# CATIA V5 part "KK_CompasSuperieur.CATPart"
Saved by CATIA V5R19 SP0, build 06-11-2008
Part number: Compas superieur
Bounding box of the stored display mesh (mm): x -108 to 108, y 1328 to 1660.464, z -2320.464 to -2052
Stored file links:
  G:\Khaled_CFAO_2011\ST2M\ST2M_GR2\aboulegue\Khaled\CAD_thinkMOTION\KK_CompasSuperieur.CATPart
  G:\Khaled_CFAO_2011\ST2M\ST2M_GR2\aboulegue\Khaled\CAD_thinkMOTION\KK_Train_Atterrissage.CATProduct
  G:\Khaled_CFAO_2011\ST2M\ST2M_GR2\aboulegue\CFAO_aboulegue\CFAO_aboulegue_fichiers_catia\Squelette_amortisseur.CATPart
  G:\Khaled_CFAO_2011\ST2M\ST2M_GR2\aboulegue\Khaled\CAD_thinkMOTION\KK_SqueletteCompas_Superieur.CATPart
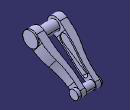
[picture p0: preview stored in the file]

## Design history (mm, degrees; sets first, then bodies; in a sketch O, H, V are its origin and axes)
Set1
  Line1 to Line3: linked copy from another document
  Plane1 "Plan compas superieur": linked copy from another document
  Point1: linked copy from another document
  Point2: linked copy from another document
  Plane2 "Plan compas superieur 2": linked copy from another document
Body1 (main body)
  Sketch1 on Plane2, origin (0, -512.64, -683.52), H (-1, 0, 0), V (0, -0.8, 0.6)
    line L1 (-50, -2312.8) -> (-50, -2408.8)
    arc A1 centre (714.0325, -2408.8) radius 764.0325 from (-50, -2408.8) to (-40.1962, -2530.8031) ccw
    point P4 (-40.1962, -2530.8031)
    arc A2 centre (-670.7452, -2632.8) radius 638.7452 from (-40.1962, -2530.8031) to (-32, -2632.8) cw
    line L2 (-32, -2632.8) -> (-32, -2728.8)
    line L3 (-32, -2728.8) -> (-64, -2728.8)
    line L4 (-64, -2728.8) -> (-64, -2632.8)
    arc A3 centre (-482.0557, -2632.8) radius 418.0557 from (-64, -2632.8) to (-82.8293, -2508.7482) ccw
    point P11 (-82.8293, -2508.7482)
    arc A4 centre (238.8266, -2408.8) radius 336.8266 from (-82.8293, -2508.7482) to (-98, -2408.8) cw
    line L5 (-98, -2408.8) -> (-98, -2312.8)
    line L6 (-98, -2312.8) -> (-50, -2312.8)
    reference projected line E1 (200, -2680.8) -> (-200, -2680.8) from Line3
    reference projected line E2 (0, -2680.8) -> (0, -2360.8) from Line1
    reference projected line E3 (0, -2680.8) -> (0, -2360.8) from Line1
    reference projected line E4 (200, -2360.8) -> (-200, -2360.8) from Line2
    length L6 = 48
    length L3 = 32
    length L2 = 96
    length L4 = 96
    length L1 = 96
    length L5 = 96
    distance P11 P4 = 48
    distance L3 E1 = 48
    distance E2 L2 = 32
    distance L1 E3 = 50
    distance L6 E4 = 48
    radius A2 = 638.7452
    vertical: L1 V, L4 V, L5 V
    tangency: A1 L1, A2 A1, L2 A2, A3 L4, A4 A3, L5 A4
    horizontal: L3 H, L6 H
    parallelism: L1 L2
  Sketch2 on Plane1, origin (0, 0, 0), H (0, 1, 0), V (0, 0, 1)
    line L1 (1650.437, -2270.3135) -> (1407.0905, -2063.4298)
    arc A1 centre (1376, -2100) radius 48 from (1407.0905, -2063.4298) to (1349.598, -2140.0866) ccw
    point P3 (1376, -2100)
    line L2 (1349.598, -2140.0866) -> (1616.3433, -2315.7717)
    arc A2 centre (1632, -2292) radius 28.4645 from (1616.3433, -2315.7717) to (1650.437, -2270.3135) ccw
    point P6 (1632, -2292)
    reference projected point E1 (1376, -2100) from Point1
    reference projected point E2 (1632, -2292) from Point2
    radius A1 = 48
    angle L1 L2 = 7
    tangency: A1 L1, A2 L2, L1 A2, L2 A1
    coincidence: E1 P3, P6 E2
  SolidCombine1: FirstComponentProfile Sketch1, FirstComponentDirection Sketch1, SecondComponentProfile Sketch2, SecondComponentDirection Sketch2
  Sketch3 on face of SolidCombine1 from Sketch1.L5, origin (98, 0, 0), H (0, 1, 0), V (0, 0, 1)
    circle A1 centre (1376, -2100) radius 32
    reference projected arc E1 centre (1376, -2100) radius 48 from (1407.0905, -2063.4298) to (1349.598, -2140.0866) ccw from edge [face of SolidCombine1 from Sketch1.L5 | face of SolidCombine1 from Sketch2.A1]
    radius A1 = 32
    concentricity: A1 E1
  Pocket1: profile Sketch3, direction (-1, 0, 0), through (limit type 6)
  Sketch4 on face of SolidCombine1 from Sketch1.L4, origin (64, 0, 0), H (0, 1, 0), V (0, 0, 1)
    circle A1 centre (1632, -2292) radius 24
    reference projected arc E1 centre (1632, -2292) radius 28.4645 from (1616.3433, -2315.7717) to (1650.437, -2270.3135) ccw from edge [face of SolidCombine1 from Sketch1.L4 | face of SolidCombine1 from Sketch2.A2]
    radius A1 = 24
    concentricity: A1 E1
  Pocket2: profile Sketch4, direction (-1, 0, 0), through (limit type 6)
  Sketch5 on face of SolidCombine1 from Sketch1.L2, origin (32, 0, 0), H (0, -1, 0), V (0, 0, 1)
    line L1 (-1460.6427, -2122.9399) -> (-1597.5251, -2239.3119)
    arc A1 centre (-1583.5955, -2255.6966) radius 21.5056 from (-1597.5251, -2239.3119) to (-1571.7665, -2273.6568) ccw
    point P3 (-1583.5955, -2255.6966)
    line L2 (-1571.7665, -2273.6568) -> (-1421.7222, -2174.8339)
    arc A2 centre (-1439.5955, -2147.6966) radius 32.4944 from (-1421.7222, -2174.8339) to (-1460.6427, -2122.9399) ccw
    point P6 (-1439.5955, -2147.6966)
    reference projected line E1 (-1632, -2292) -> (-1376, -2100) from Line1
    reference projected line E2 (-1632, -2292) -> (-1376, -2100) from Line1
    reference projected circle E3 centre (-1376, -2100) radius 32 from edge [face of Pocket1 from Sketch3.A1 | face of SolidCombine1 from Sketch1.L1]
    reference projected circle E4 centre (-1632, -2292) radius 24 from edge [face of Pocket2 from Sketch4.A1 | face of SolidCombine1 from Sketch1.L2]
    angle L2 L1 = 7
    distance P3 P6 = 180
    distance A2 E3 = 15
    distance E4 A1 = 15
    tangency: A1 L1, A2 L2, L2 A1, L1 A2
    coincidence: P3 E1, P6 E2
  Pocket3: profile Sketch5, direction (1, 0, 0), length 25
  Mirror1: of SolidCombine1, Pocket1, Pocket2, Pocket3, about Plane1
  Sketch6 on face of SolidCombine1 from Sketch1.L5, origin (98, 0, 0), H (0, 1, 0), V (0, 0, 1)
    circle A1 centre (1376, -2100) radius 48
    reference projected circle E1 centre (1376, -2100) radius 32 from edge [face of SolidCombine1 from Sketch1.L5 | face of Pocket1 from Sketch3.A1]
    radius A1 = 48
    concentricity: A1 E1
  Pad1: profile Sketch6, direction (1, 0, 0), length 10
  Sketch7 on start face of Pad1, origin (98, 0, 0), H (0, -1, 0), V (0, 0, 1)
    circle A1 centre (-1376, -2100) radius 32
    reference projected circle E1 centre (-1376, -2100) radius 32 from edge [start face of Pad1 | face of Pocket1 from Sketch3.A1]
    coincidence: E1 A1
  Pad2: profile Sketch7, direction (-1, 0, 0), length 206
  Sketch8 on face of SolidCombine1 from Sketch1.L4, origin (64, 0, 0), H (0, 1, 0), V (0, 0, 1)
    circle A1 centre (1632, -2292) radius 28.4645
    reference projected arc E1 centre (1632, -2292) radius 28.4645 from (1616.3433, -2315.7717) to (1650.437, -2270.3135) ccw from edge [face of SolidCombine1 from Sketch1.L4 | face of SolidCombine1 from Sketch2.A2]
    coincidence: E1 A1
  Pad3: profile Sketch8, direction (1, 0, 0), length 20
  Sketch9 on start face of Pad3, origin (64, 0, 0), H (0, -1, 0), V (0, 0, 1)
    circle A1 centre (-1632, -2292) radius 24
    reference projected circle E1 centre (-1632, -2292) radius 24 from edge [start face of Pad3 | face of Pocket2 from Sketch4.A1]
    coincidence: E1 A1
  Pad4: profile Sketch9, direction (-1, 0, 0), length 138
